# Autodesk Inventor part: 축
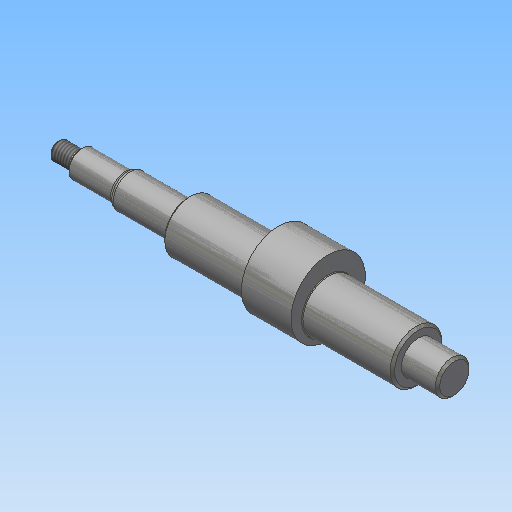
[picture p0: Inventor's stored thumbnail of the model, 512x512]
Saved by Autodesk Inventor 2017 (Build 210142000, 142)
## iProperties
Created: 2015-12
Part Number: 축
Document SubType Name: Modeling
Designer: mdu
Density: 7.86 g/cm^3
Material: 강철, 연강
Appearance: 강철
Mass: 489.928 g
Surface Area: 127.026 cm^2
Volume: 62.3318 cm^3
Author: mdu
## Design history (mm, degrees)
sketch "스케치1"
  geometry: L1 (62, 100.9)-(62, 67.1) reference; L2 (51, 101.2)-(51, 84) reference; L3 (-51, 84)-(-51, 101.2) reference; L4 (-62, 67.1)-(-62, 100.9) reference; L5 (-51.6, 91.5)-(-61.4, 91.5) reference; L6 (51.6, 91.5)-(61.4, 91.5) reference; L7 (67, 84)-(-109, 84); L8 (-77, 64.201)-(-77, 103.799) reference; L9 (67, 84)-(67, 91.5); L10 (67, 91.5)-(51, 91.5); L11 (51, 91.5)-(51, 95.5); L12 (51, 95.5)-(-51, 95.5); L13 (-51, 95.5)-(-51, 91.5); L14 (-51, 91.5)-(-79, 91.5); L15 (-79, 91.5)-(-79, 90); L16 (-79, 90)-(-99, 90); L17 (-99, 90)-(-99, 88); L18 (-99, 88)-(-109, 88); L19 (-109, 88)-(-109, 84); 2 further points
  constraints: 28 end point, 7 parallel, 5 point on line, 4 perpendicular, 2 collinear, 2 horizontal, 1 midpoint, 4 other
  dimensions: "d0" = 5 distance from line of L7.start L1; "d2" = 2 distance between parallel lines of L15 L8; "d3" = 23 diameter of L12 L7; "d4" = 12 diameter of L16 L7; "d7" = 20 distance of L15.end L16.end; "d8" = 10 distance between parallel lines of L17 L19; "d9" = 8 diameter of L18 L7
revolve "회전1" sketch "스케치1" stored, may be unused: angle "d10" = 90 deg
sketch "스케치2"
  geometry: C1 r 11.5 at (84, 0) reference; C2 r 11.5 at (84, 0) reference; C3 r 16.5 at (87, 0); 1 further point
  constraints: 1 centre point, 1 horizontal alignment
  dimensions: "d11" = 33 diameter of C3; "d12" = 3 distance of C3.centre C1.centre
extrude "돌출1" join sketch "스케치2" stored distance "d13" = 22; taper "d14" = 0 deg
chamfer "모따기1" distance "d15" = 1; stored, may be unused: second distance "d16" = 2, angle "d17" = 45 deg
feature "스레드1" dims "d18" = 8, "d19" = 0
node "작업 평면1"
sketch "스케치3"
  geometry: L1 (-5, -2)-(3, -2); L2 (3, 2)-(-5, 2); L3 (-10, -5)-(-10, 5) reference; A1 r 2 centre (3, 0) between (3, -2) and (3, 2); A2 r 2 centre (-5, 0) between (-5, 2) and (-5, -2); 2 further points
  constraints: 4 end point, 4 point on circle, 4 tangent, 2 centre point, 1 horizontal, 1 horizontal alignment, 1 midpoint, 1 parallel
  dimensions: "d20" = 4 distance between parallel lines of L1 L2; "d21" = 12 dimension on A1 A2; "d22" = 3 distance edge to line of A2 L3
extrude "돌출2" cut sketch "스케치3" distance "d23" = 2.5; taper "d24" = 0 deg
fillet "모깎기1" dims "d25" = 0.3
chamfer "모따기2" distance "d27" = 1.65; stored, may be unused: second distance "d28" = 2, angle "d29" = 30 deg
fillet "모깎기3" dims "d30" = 2
node "솔리드1"
node "참조1"
node "참조2"
node "참조3"
node "참조4"
node "참조5"
node "투영된 루프1"
